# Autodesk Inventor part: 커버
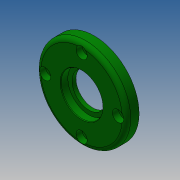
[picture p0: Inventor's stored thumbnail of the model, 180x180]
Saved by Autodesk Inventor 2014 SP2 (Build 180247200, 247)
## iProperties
Created: 2019-09
Part Number: 커버
Material: 알루미늄 6061
Document SubType Name: Modeling
Designer: mduedu
Density: 2.71 g/cm^3
Mass: 60.8496 g
Surface Area: 89.5893 cm^2
Volume: 22.4537 cm^3
Appearance: 진녹색
Author: mduedu
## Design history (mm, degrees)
sketch "스케치1"
  geometry: C1 r 32 at (0, 0); 1 further point
  constraints: 1 centre point, 1 coincident
  dimensions: "d0" = 64 diameter of C1
extrude "돌출1" new body sketch "스케치1" distance "d1" = 9; taper "d2" = 0 deg
sketch "스케치2"
  geometry: C1 r 21 at (0, 0); 1 further point
  constraints: 1 centre point, 1 coincident
  dimensions: "d3" = 42 diameter of C1
extrude "돌출2" join sketch "스케치2" distance "d4" = 3; taper "d5" = 0 deg
hole "구멍1" diameter "d8" = 24; stored, may be unused: countersink angle "d12" = 90 deg, drill point angle "d14" = 118 deg; dims "d6" = 10, "d7" = 10, "d9" = 6, "d10" = 30, "d11" = 5.2, "d13" = 8
hole "구멍2" diameter "d17" = 37; stored, may be unused: countersink angle "d21" = 90 deg, drill point angle "d23" = 0 deg; dims "d15" = 10, "d16" = 10, "d18" = 6, "d19" = 30, "d20" = 5.2, "d22" = 4
fillet "모깎기1" dims "d24" = 3
fillet "모깎기2" dims "d25" = 3
chamfer "모따기1" distance "d27" = 0.5; stored, may be unused: second distance "d28" = 2, angle "d29" = 30 deg
chamfer "모따기2" distance "d30" = 1; stored, may be unused: second distance "d31" = 2, angle "d32" = 30 deg
sketch "스케치3" dims "d33" = 52
  geometry: 3 further points
  constraints: 2 vertical alignment, 1 coincident, 2 other
hole "구멍3" sketch "스케치3" at (0, 26) diameter "d34" = 4.5; stored, may be unused: countersink angle "d38" = 90 deg, drill point angle "d40" = 0 deg; dims "d35" = 6, "d36" = 8, "d37" = 4.4, "d39" = 4
node "솔리드1"
pattern_circular "원형 패턴1" dims angle "d42" = 360 deg
